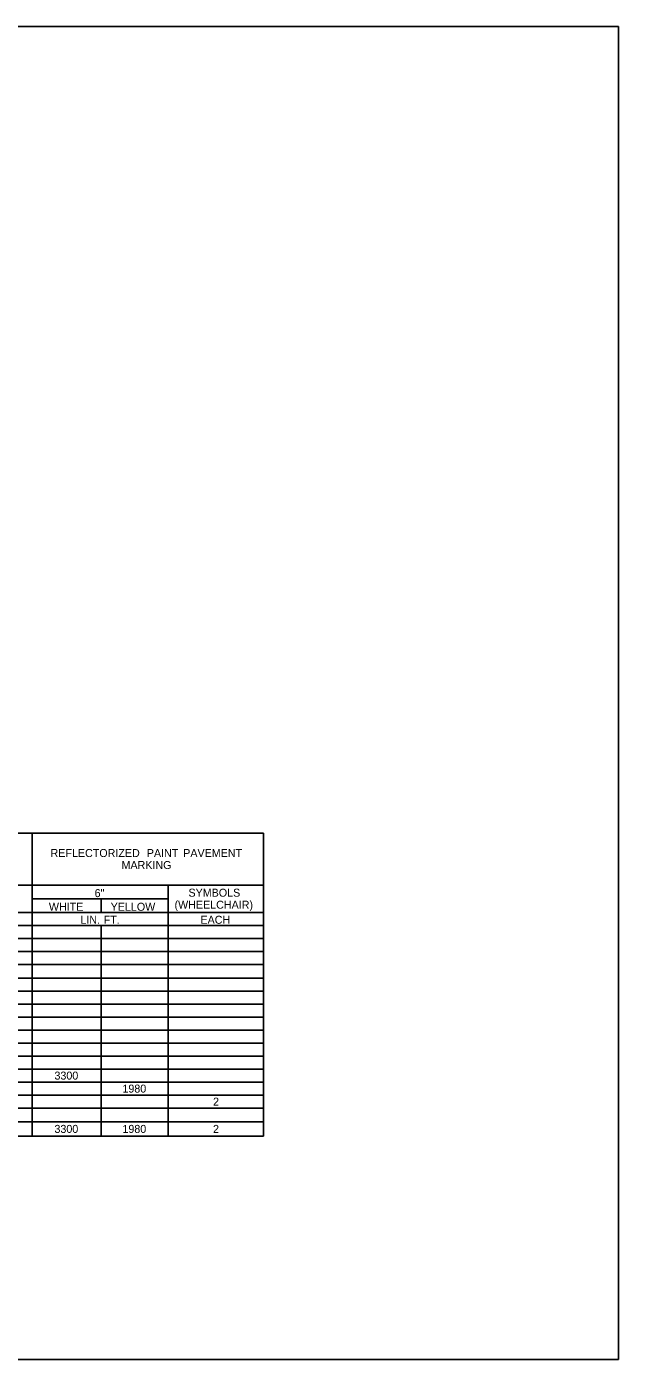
# Model space of a CAD drawing. Extents: x 2261867 to 2275370, y -3124789 to -3122260.
# Drawn here: x 2263074 to 2263517, y -3124789 to -3123790 of the extents above; entities that cross this region are included whole.
import ezdxf

# ---------------------------------------------------------------- set-up
doc = ezdxf.new("R2010")
doc.units = 0
doc.layers.add('Default', color=7, linetype='Continuous')
doc.layers.add('DSN_DRFT_Named-Boundary', color=7, linetype='Continuous')

msp = doc.modelspace()

# ---------------------------------------------------------------- linework, layer by layer
at = {"layer": 'Default'}
for p, q in [((2262050.38, -3124394.19), (2263251.58, -3124394.19)), ((2263078.03, -3124621.37), (2263078.03, -3124394.19)), ((2263251.58, -3124621.37), (2263251.58, -3124394.19)), ((2263251.58, -3124621.37), (2263251.58, -3124394.19)), ((2262642.2, -3124433.19), (2263251.58, -3124433.19)), ((2263179.92, -3124621.37), (2263179.92, -3124433.19)), ((2263078.03, -3124443.43), (2263179.92, -3124443.43)), ((2263129.7, -3124453.67), (2263129.7, -3124443.43)), ((2262359.94, -3124453.67), (2263251.58, -3124453.67)), ((2262927.39, -3124453.67), (2263179.92, -3124453.67)), ((2263179.92, -3124453.67), (2263251.58, -3124453.67)), ((2262050.38, -3124463.42), (2263251.58, -3124463.42)), ((2263129.7, -3124621.37), (2263129.7, -3124463.42)), ((2263179.92, -3124621.37), (2263179.92, -3124463.42)), ((2262050.38, -3124473.17), (2263251.58, -3124473.17)), ((2262050.38, -3124482.92), (2263251.58, -3124482.92)), ((2262050.38, -3124492.67), (2263251.58, -3124492.67)), ((2262050.38, -3124502.9), (2263251.58, -3124502.9)), ((2262050.38, -3124512.65), (2263251.58, -3124512.65)), ((2262050.38, -3124522.4), (2263251.58, -3124522.4)), ((2262050.38, -3124532.15), (2263251.58, -3124532.15)), ((2262050.38, -3124541.9), (2263251.58, -3124541.9)), ((2262050.38, -3124551.65), (2263251.58, -3124551.65)), ((2262050.38, -3124561.4), (2263251.58, -3124561.4)), ((2262050.38, -3124571.15), (2263251.58, -3124571.15)), ((2262050.38, -3124580.9), (2263251.58, -3124580.9)), ((2262050.38, -3124590.65), (2263251.58, -3124590.65)), ((2262050.38, -3124600.4), (2263251.58, -3124600.4)), ((2262050.38, -3124610.64), (2263251.58, -3124610.64)), ((2262050.38, -3124621.37), (2263251.58, -3124621.37))]:
    msp.add_line(p, q, dxfattribs=at)
at = {"layer": 'DSN_DRFT_Named-Boundary'}
msp.add_lwpolyline([(2261867.48, -3124788.75), (2263517.48, -3124788.75), (2263517.48, -3123789.69), (2261867.48, -3123789.69)], close=True, dxfattribs=at)

# ---------------------------------------------------------------- texts
at = {"layer": 'Default'}
for s, p in [('REFLECTORIZED', (2263091.82, -3124412.19)), (' PAINT', (2263161.74, -3124412.19)), (' PAVEMENT', (2263189.05, -3124412.19)), ('MARKING', (2263145.03, -3124421.19)), ('6"', (2263124.86, -3124442.23)), ('SYMBOLS', (2263195.22, -3124441.93)), ('WHITE', (2263090.57, -3124452.47)), ('YELLOW', (2263136.88, -3124452.47)), ('(WHEELCHAIR)', (2263184.76, -3124450.93)), ('LIN.', (2263114.18, -3124462.22)), (' FT.', (2263129.44, -3124462.22)), ('EACH', (2263204.19, -3124462.22)), ('3300', (2263094.75, -3124579.03)), ('1980', (2263145.69, -3124588.78)), ('2', (2263213.64, -3124598.53)), ('3300', (2263094.75, -3124619)), ('1980', (2263145.7, -3124619)), ('2', (2263213.63, -3124619))]:
    msp.add_text(s, height=6, dxfattribs=at).set_placement(p)

doc.saveas('drawing.dxf')
